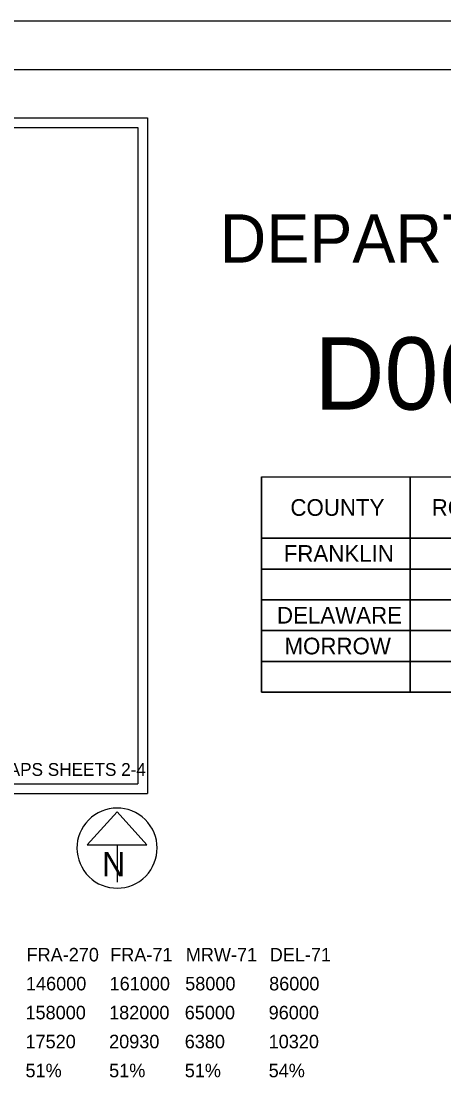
# Model space of a CAD drawing. Extents: x 0 to 34, y 0 to 22.
# Drawn here: x 7.69 to 12.07, y 10.98 to 22 of the extents above; entities that cross this region are included whole.
import ezdxf

# ---------------------------------------------------------------- set-up
doc = ezdxf.new("R2010")
doc.units = 0
for name, color, linetype in [('Default', 7, 'Continuous'), ('SH_Border', 7, 'Continuous'), ('SH_Cut_Line', 7, 'Continuous'), ('SH_Data', 7, 'Continuous'), ('SH_Text', 7, 'Continuous')]:
    doc.layers.add(name, color=color, linetype=linetype)

msp = doc.modelspace()

# ---------------------------------------------------------------- linework, layer by layer
at = {"layer": 'Default'}
for p, q in [((10.182, 17.282), (23.457, 17.282)), ((10.182, 17.282), (10.182, 15.051)), ((11.719, 17.282), (11.719, 15.051)), ((10.182, 16.644), (23.457, 16.644)), ((10.182, 16.326), (23.457, 16.326)), ((10.182, 16.007), (23.457, 16.007)), ((10.182, 15.688), (23.457, 15.688)), ((10.182, 15.369), (23.457, 15.369)), ((10.182, 15.051), (23.457, 15.051))]:
    msp.add_line(p, q, dxfattribs=at)
for points in [[(10.182, 17.282), (11.719, 17.282), (11.719, 16.644), (10.182, 16.644)], [(11.719, 17.282), (12.938, 17.282), (12.938, 16.644), (11.719, 16.644)], [(10.182, 16.644), (11.719, 16.644), (11.719, 16.326), (10.182, 16.326)], [(11.719, 16.644), (12.938, 16.644), (12.938, 16.326), (11.719, 16.326)], [(10.182, 16.326), (11.719, 16.326), (11.719, 16.007), (10.182, 16.007)], [(11.719, 16.326), (12.938, 16.326), (12.938, 16.007), (11.719, 16.007)], [(10.182, 16.007), (11.719, 16.007), (11.719, 15.688), (10.182, 15.688)], [(11.719, 16.007), (12.938, 16.007), (12.938, 15.688), (11.719, 15.688)], [(10.182, 15.688), (11.719, 15.688), (11.719, 15.369), (10.182, 15.369)], [(11.719, 15.688), (12.938, 15.688), (12.938, 15.369), (11.719, 15.369)], [(10.182, 15.369), (11.719, 15.369), (11.719, 15.051), (10.182, 15.051)], [(11.719, 15.369), (12.938, 15.369), (12.938, 15.051), (11.719, 15.051)]]:
    msp.add_lwpolyline(points, close=True, dxfattribs=at)
at = {"layer": 'SH_Border'}
msp.add_lwpolyline([(1.5, 21.5), (33.5, 21.5), (33.5, 0.5), (1.5, 0.5)], close=True, dxfattribs=at)
at = {"layer": 'SH_Cut_Line'}
msp.add_lwpolyline([(0, 0), (34, 0), (34, 22), (0, 22)], close=True, dxfattribs=at)
at = {"layer": 'SH_Data'}
for p, q in [((2, 21), (9, 21)), ((9, 21), (9, 14)), ((2.1, 20.9), (8.9, 20.9)), ((8.9, 20.9), (8.9, 14.1)), ((2, 14), (9, 14)), ((2.1, 14.1), (8.9, 14.1)), ((8.685, 13.809), (8.377, 13.468)), ((8.992, 13.468), (8.685, 13.809)), ((8.377, 13.468), (8.992, 13.468)), ((8.685, 13.468), (8.685, 13.081)), ((8.685, 13.435), (8.685, 13.435)), ((8.685, 13.435), (8.685, 13.435))]:
    msp.add_line(p, q, dxfattribs=at)
msp.add_arc((8.685, 13.435), 0.415, 129.7798, 129.7633, dxfattribs=at)

# ---------------------------------------------------------------- texts
at = {"layer": 'Default'}
for s, p in [('COUNTY', (10.48, 16.877)), ('ROUTE', (11.943, 16.877)), ('FRANKLIN', (10.411, 16.401)), ('DELAWARE', (10.341, 15.761)), ('MORROW', (10.419, 15.442))]:
    msp.add_text(s, height=0.1725, dxfattribs=at).set_placement(p)
at = {"layer": 'SH_Data'}
for s, height, p in [('SEE LOCATION MAPS SHEETS 2-4', 0.13282, (6.053, 14.183)), ('N', 0.25, (8.529, 13.144))]:
    msp.add_text(s, height=height, dxfattribs=at).set_placement(p)
at = {"layer": 'SH_Text'}
for s, height, p in [('DEPARTMENT OF TRANSPORTATION', 0.5, (9.747, 19.5)), ('D06-SP-FY2024 PRIORITY', 0.75, (10.73, 17.977)), ('FRA-270', 0.14, (7.748, 12.261)), ('FRA-71', 0.14, (8.614, 12.261)), ('MRW-71', 0.14, (9.397, 12.261)), ('DEL-71', 0.14, (10.266, 12.261)), ('146000', 0.14, (7.742, 11.961)), ('161000', 0.14, (8.608, 11.961)), ('58000', 0.14, (9.391, 11.961)), ('86000', 0.14, (10.26, 11.961)), ('158000', 0.14, (7.737, 11.661)), ('182000', 0.14, (8.603, 11.661)), ('65000', 0.14, (9.386, 11.661)), ('96000', 0.14, (10.255, 11.661)), ('17520', 0.14, (7.737, 11.361)), ('20930', 0.14, (8.603, 11.361)), ('6380', 0.14, (9.386, 11.361)), ('10320', 0.14, (10.255, 11.361)), ('51%', 0.14, (7.737, 11.061)), ('51%', 0.14, (8.603, 11.061)), ('51%', 0.14, (9.386, 11.061)), ('54%', 0.14, (10.255, 11.061))]:
    msp.add_text(s, height=height, dxfattribs=at).set_placement(p)

doc.saveas('drawing.dxf')
